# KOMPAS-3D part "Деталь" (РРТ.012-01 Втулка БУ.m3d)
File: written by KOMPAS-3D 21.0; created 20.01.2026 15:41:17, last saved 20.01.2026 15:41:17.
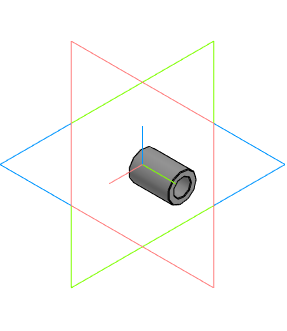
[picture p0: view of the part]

Document properties: Автор: Alexey; Полное имя файла: C:\Users\Alexey\Desktop\РРТ.012-01 Втулка БУ.m3d

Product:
- Part/product: Деталь
    Масса: 0.005513

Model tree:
1. Эскиз:1
2. Элемент выдавливания:1
     Расстояние 1 = 14
3. Фаска:1  (with: Элемент выдавливания:1)
     Угол = 45; Длина 1 = 0.2; Длина 2 = 0.2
